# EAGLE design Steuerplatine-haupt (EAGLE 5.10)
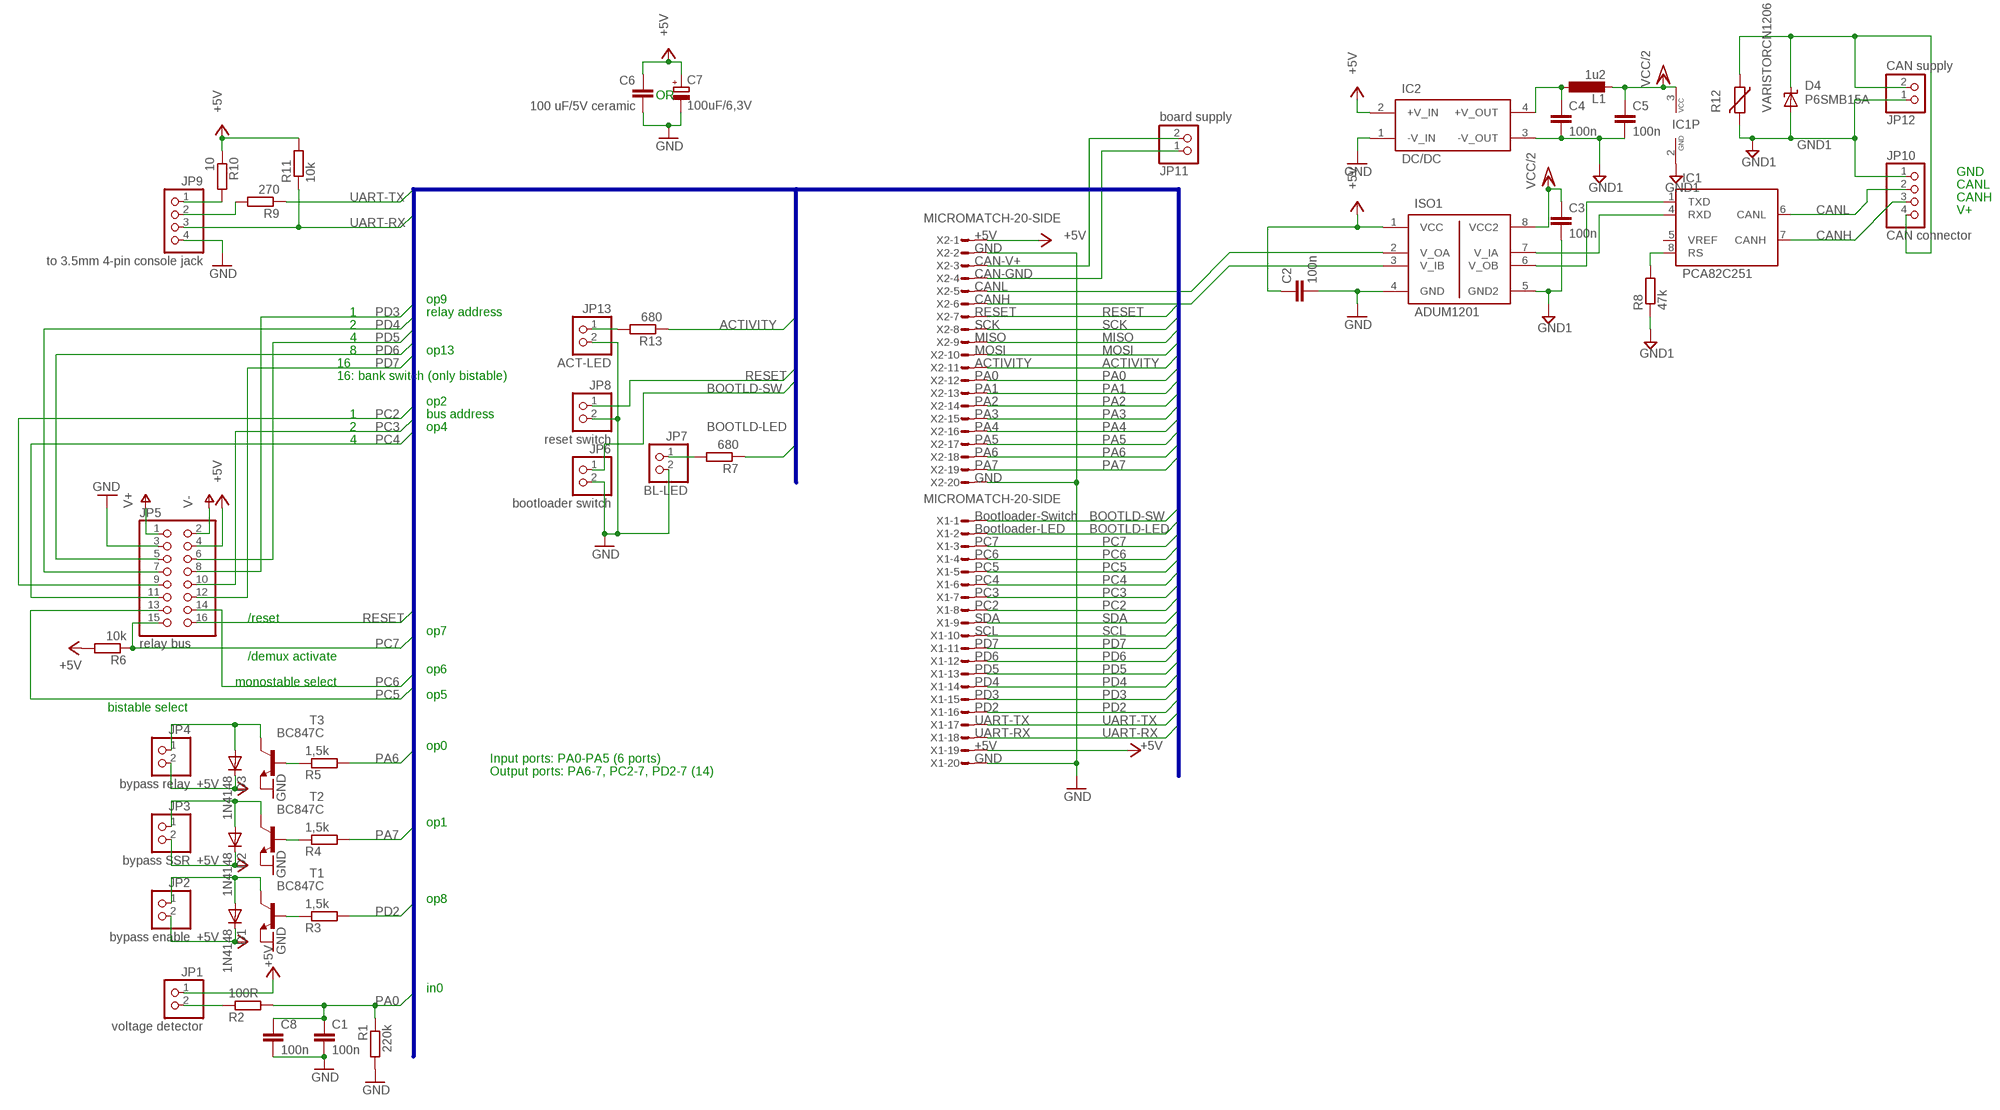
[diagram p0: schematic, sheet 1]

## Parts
C1  100n  C-EUC0805  [C0805]
C2  100n  C-EUC0805  [C0805]
C3  100n  C-EUC0805  [C0805]
C4  100n  C-EUC0805  [C0805]
C5  100n  C-EUC0805  [C0805]
C6  100 uF/5V ceramic  C-EUC1206  [C1206]
C7  100uF/6,3V  CPOL-EUD  [PANASONIC_D]
C8  100n  C-EUC0805  [C0805]
D1  1N4148  DIODE-SOD323-W  [SOD323-W]
D2  1N4148  DIODE-SOD323-W  [SOD323-W]
D3  1N4148  DIODE-SOD323-W  [SOD323-W]
D4  P6SMB15A  P6SMBXXA  [SMB]
IC1  PCA82C251  PCA82C250  [DIL08]
IC2  DC/DC  [DCDC-SIL4]
ISO1  ADUM1201  [SO08]
JP1  voltage detector  PINHD-1X2  [1X02]
JP2  bypass enable  PINHD-1X2  [1X02]
JP3  bypass SSR  PINHD-1X2  [1X02]
JP4  bypass relay  PINHD-1X2  [1X02]
JP5  relay bus  PINHD-2X8/90  [2X08/90]
JP6  bootloader switch  PINHD-1X2  [1X02]
JP7  BL-LED  PINHD-1X2  [1X02]
JP8  reset switch  PINHD-1X2  [1X02]
JP9  to 3.5mm 4-pin console jack  PINHD-1X4  [1X04]
JP10  CAN connector  PINHD-1X4  [1X04]
JP11  board supply  PINHD-1X2  [1X02]
JP12  CAN supply  PINHD-1X2  [1X02]
JP13  ACT-LED  PINHD-1X2  [1X02]
L1  1u2  L-EUL3216C  [L3216C]
R1  220k  R-EU_R0805  [R0805]
R2  100R  R-EU_R0805  [R0805]
R3  1,5k  R-EU_R0805  [R0805]
R4  1,5k  R-EU_R0805  [R0805]
R5  1,5k  R-EU_R0805  [R0805]
R6  10k  R-EU_R0805  [R0805]
R7  680  R-EU_R0805  [R0805]
R8  47k  R-EU_R0805  [R0805]
R9  270  R-EU_R0805  [R0805]
R10  10  R-EU_R0805  [R0805]
R11  10k  R-EU_R0805  [R0805]
R12  VARISTORCN1206  [CT/CN1206]
R13  680  R-EU_R0805  [R0805]
T1  BC847C  BC847BSMD  [SOT23]
T2  BC847C  BC847BSMD  [SOT23]
T3  BC847C  BC847BSMD  [SOT23]
X1  MICROMATCH-20-SIDE  [MICROMATCH-20-SIDE]
X2  MICROMATCH-20-SIDE  [MICROMATCH-20-SIDE]

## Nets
+5V: C2.1 C6.1 C7.+ D1.C D2.C D3.C IC2.2(+V_IN) ISO1.1(VCC) JP1.1 JP2.2 JP3.2 JP4.2 JP5.4 R6.2 R10.1 R11.2 X1.19 X2.1
ACTIVITY: R13.1 X2.11
BOOTLD-LED: R7.1 X1.2
BOOTLD-SW: JP6.1 X1.1
CAN-GND: JP11.1 X2.4
CAN-V+: JP11.2 X2.3
CAN_CONN_V+ [Power]: D4.C JP10.4 JP12.2 R12.1
CANH: IC1.7(CANH) JP10.3
CANH_TXD: ISO1.3(V_IB) X2.6
CANL: IC1.6(CANL) JP10.2
CANL_RXD: ISO1.2(V_OA) X2.5
GND: C1.2 C2.2 C6.2 C7.- C8.2 IC2.1(-V_IN) ISO1.4(GND) JP5.3 JP6.2 JP7.2 JP8.2 JP9.4 JP13.2 R1.2 T1.2(E) T2.2(E) T3.2(E) X1.20 X2.2 X2.20
GND1: C3.2 C4.2 C5.2 D4.A IC1.2(GND) IC2.3(-V_OUT) ISO1.5(GND2) JP10.1 JP12.1 R8.1 R12.2
MISO: X2.9
MOSI: X2.10
N$1: JP1.2 R2.1
N$2: JP9.2 R9.2
N$3: JP9.1 R10.2
N$4: JP13.1 R13.2
N$6: R3.1 T1.1(B)
N$7: D1.A JP2.1 T1.3(C)
N$8: IC1.4(RXD) ISO1.7(V_IA)
N$9: JP7.1 R7.2
N$10: R4.1 T2.1(B)
N$11: D3.A JP4.1 T3.3(C)
N$12: IC1.1(TXD) ISO1.6(V_OB)
N$13: D2.A JP3.1 T2.3(C)
N$14: C4.1 IC2.4(+V_OUT) L1.1
N$15: IC1.8(RS) R8.2
N$48: R5.1 T3.1(B)
PA0: C1.1 C8.1 R1.1 R2.2 X2.12
PA1: X2.13
PA2: X2.14
PA3: X2.15
PA4: X2.16
PA5: X2.17
PA6: R5.2 X2.18
PA7: R4.2 X2.19
PC2: JP5.9 X1.8
PC3: JP5.10 X1.7
PC4: JP5.11 X1.6
PC5: JP5.13 X1.5
PC6: JP5.14 X1.4
PC7: JP5.15 R6.1 X1.3
PD2: R3.2 X1.16
PD3: JP5.8 X1.15
PD4: JP5.7 X1.14
PD5: JP5.6 X1.13
PD6: JP5.5 X1.12
PD7: JP5.12 X1.11
RESET: JP5.16 JP8.1 X2.7
SCK: X2.8
SCL: X1.10
SDA: X1.9
UART-RX: JP9.3 R11.1 X1.18
UART-TX: R9.1 X1.17
V+: JP5.1
V-: JP5.2
VCC/2: C3.1 C5.1 IC1.3(VCC) ISO1.8(VCC2) L1.2
Unconnected: IC1.5(VREF)

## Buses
PA[0..7],PC[2..7],PD[2..7],SCK,MISO,MOSI,CAN-CS,BOOTLD-SW,CAN-INT,BOOTLD-LED,ACTIVITY,SDA,SCL,UART-RX,UART-TX,CLK,RESET

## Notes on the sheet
- OR
- GND
- CANL
- CANH
- V+
- +5V
- GND
- CAN-V+
- CAN-GND
- CANL
- op9 | CANH
- 1 | relay address | RESET
- 2 | SCK
- 4 | MISO
- 8 | op13 | MOSI
- 16 | ACTIVITY
- 16: bank switch (only bistable) | PA0
- PA1
- op2 | PA2
- 1 | bus address | PA3
- 2 | op4 | PA4
- 4 | PA5
- PA6
- PA7
- GND
- Bootloader-Switch
- Bootloader-LED
- PC7
- PC6
- PC5
- PC4
- PC3
- PC2
- /reset | SDA
- op7 | SCL
- PD7
- /demux activate | PD6
- op6 | PD5
- monostable select | PD4
- op5 | PD3
- bistable select | PD2
- UART-TX
- UART-RX
- op0 | +5V
- Input ports: PA0-PA5 (6 ports) | GND
- Output ports: PA6-7, PC2-7, PD2-7 (14)
- op1
- op8
- in0

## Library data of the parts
C1-C6 C8 = rcl:C-EU: CAPACITOR, European symbol
C7 = rcl:CPOL-EU: POLARIZED CAPACITOR, European symbol
D1-D3 = diode:DIODE-: DIODE
D4 = 11my-ICs:P6SMBXXA: Suppressor diode
IC1 = 11my-CAN:PCA82C250: PCA82C250 CAN Bustreiber
IC2 = 11my-ICs:DC/DC
ISO1 = 11my-ICs:ADUM1201: ADuM1201 Dual-Channel Digital Isolators zu beziehen per Sample oder bei Farnell
JP1-JP4 JP6-JP8 JP11-JP13 = pinhead:PINHD-1X2: PIN HEADER
JP5 = pinhead:PINHD-2X8: PIN HEADER
JP9 JP10 = pinhead:PINHD-1X4: PIN HEADER
L1 = rcl:L-EU: INDUCTOR, European symbol
R1-R11 R13 = rcl:R-EU_: RESISTOR, European symbol
R12 = varistor:VARISTOR: VARISTOR
T1-T3 = transistor-npn:BC847*: NPN Transistor
X1 X2 = apbteam_con-amp-micromatch:MICROMATCH-20: Micro-MaTch 20 Straight connector: Suited for both, female and male.

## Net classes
0 default: width 0.15 mm, clearance 0.3 mm
1 Power: width 0.5 mm, clearance 0.3 mm

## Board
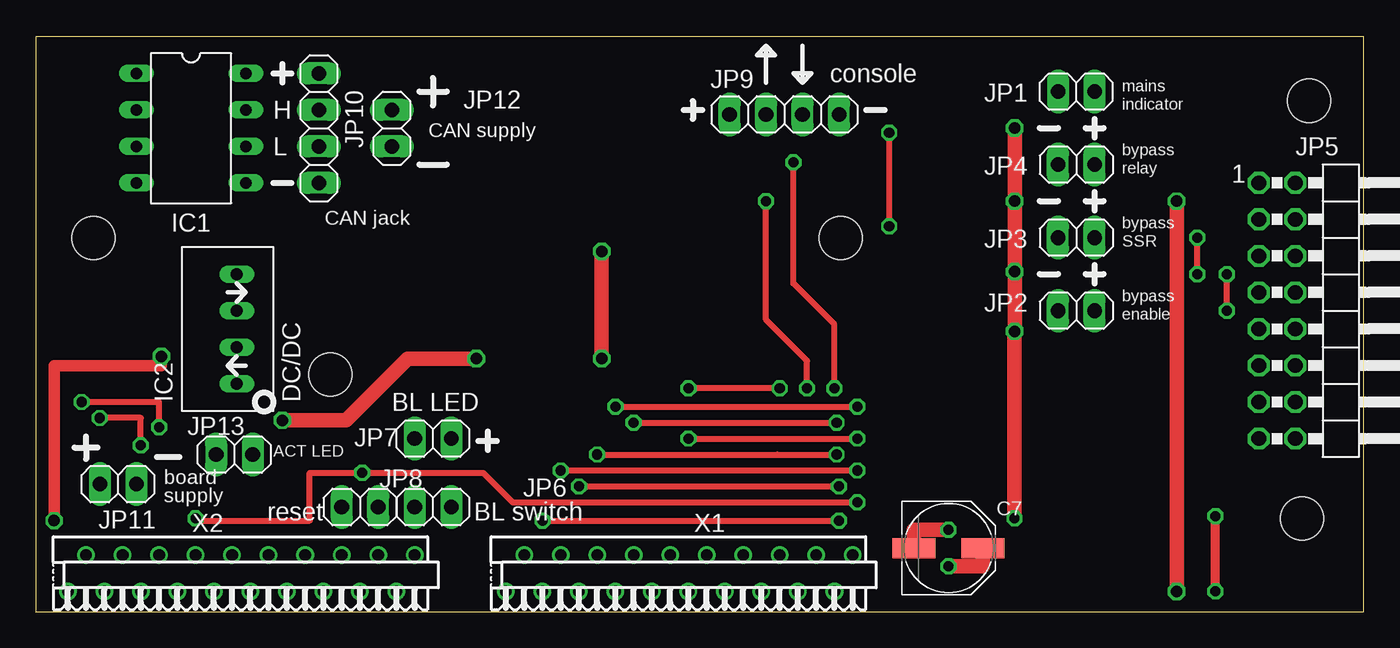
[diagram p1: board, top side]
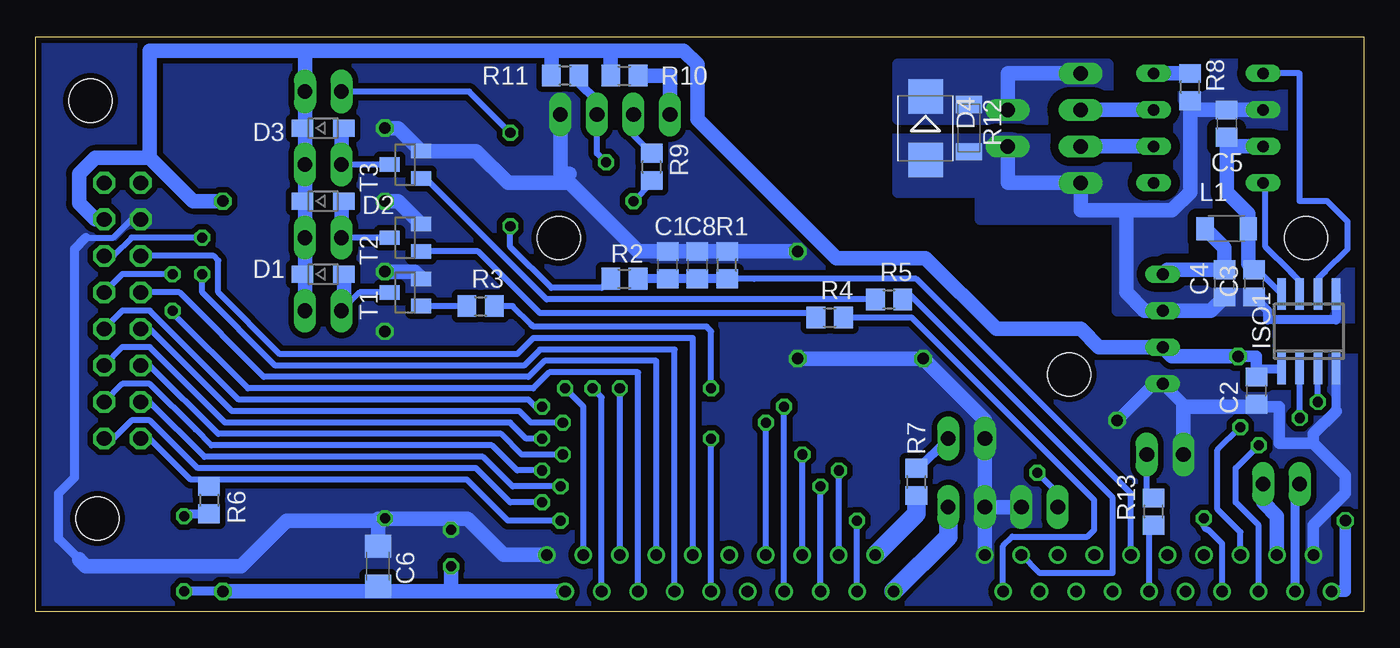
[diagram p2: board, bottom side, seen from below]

Size 92.38 x 40 mm. Coordinates in mm from the lower left corner, seen from the top.
Outline: 0,0 92.38,0 92.38,40 0,40 0,0
Copper layers (1+2*15+16): Top 0.035mm / dielectric 0.36mm / layer 2 0.018mm / dielectric 0.71mm / layer 15 0.018mm / dielectric 0.36mm / Bottom 0.035mm
Design rules "q-print.info *": minimum track width 6mil, minimum drill 0.3mm, track to track 6mil, track to pad 6mil, pad to pad 6mil, via to via 6mil, smd to smd 6mil, copper to edge 8mil, drill to drill 10mil, minimum pad ring 8mil, minimum via ring 8mil, stop-mask expansion 4mil, vias tented up to drill 16mil, thermal gap 10mil
Holes 3 mm at 4,26 56,26 20.48,16.51 88.58,35.56 88.11,6.51

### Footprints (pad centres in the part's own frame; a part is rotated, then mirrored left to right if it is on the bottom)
C0805 = smd 1.3 x 1.5: 1 -0.95,0; 2 0.95,0
C1206 = smd 1.6 x 1.8: 1 -1.4,0; 2 1.4,0
PANASONIC_D = smd 3 x 1.4: + 2.4,0; - -2.4,0
SOD323-W = smd 1.5 x 1.2: A 1.45,0; C -1.45,0
SMB = smd 2.4 x 2.4: A 2.2,0; C -2.2,0
DIL08 = drill 0.813 long: 1 -3.81,-3.81; 2 -1.27,-3.81; 3 1.27,-3.81; 4 3.81,-3.81; 5 3.81,3.81; 6 1.27,3.81; 7 -1.27,3.81; 8 -3.81,3.81
DCDC-SIL4 = drill 0.813 long: 1 -3.81,0; 2 -1.27,0; 3 1.27,0; 4 3.81,0
SO08 = smd 0.6 x 2.2: 1 -1.905,-2.6; 2 -0.635,-2.6; 3 0.635,-2.6; 4 1.905,-2.6; 5 1.905,2.6; 6 0.635,2.6; 7 -0.635,2.6; 8 -1.905,2.6
1X02 = drill 1.016 long: 1 -1.27,0; 2 1.27,0
2X08/90 = drill 1.016 octagon: 1 -8.89,-6.35; 2 -8.89,-3.81; 3 -6.35,-6.35; 4 -6.35,-3.81; 5 -3.81,-6.35; 6 -3.81,-3.81; 7 -1.27,-6.35; 8 -1.27,-3.81; 9 1.27,-6.35; 10 1.27,-3.81; 11 3.81,-6.35; 12 3.81,-3.81; 13 6.35,-6.35; 14 6.35,-3.81; 15 8.89,-6.35; 16 8.89,-3.81
1X04 = drill 1.016 long: 1 -3.81,0; 2 -1.27,0; 3 1.27,0; 4 3.81,0
L3216C = smd 1.2 x 1.6: 1 -1.5,0; 2 1.5,0
R0805 = smd 1.3 x 1.5: 1 -0.95,0; 2 0.95,0
CT/CN1206 = smd 1.2 x 1.8: 1 -1.65,0; 2 1.65,0
SOT23 = smd 1 x 1.4: 1 -0.95,-1.1; 2 0.95,-1.1; 3 0,1.1
MICROMATCH-20-SIDE = drill 0.813 round: 1 12.065,1.27; 2 10.795,-1.27; 3 9.525,1.27; 4 8.255,-1.27; 5 6.985,1.27; 6 5.715,-1.27; 7 4.445,1.27; 8 3.175,-1.27; 9 1.905,1.27; 10 0.635,-1.27; 11 -0.635,1.27; 12 -1.905,-1.27; 13 -3.175,1.27; 14 -4.445,-1.27; 15 -5.715,1.27; 16 -6.985,-1.27; 17 -8.255,1.27; 18 -9.525,-1.27; 19 -10.795,1.27; 20 -12.065,-1.27

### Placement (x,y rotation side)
C1  48.42,24.13 90 bottom
C2  7.46,15.4 270 bottom
C3  7.62,22.86 270 bottom
C4  9.68,22.86 270 bottom
C5  9.53,33.97 90 bottom
C6  68.58,3.18 90 bottom
C7  63.5,4.45 0 top
C8  46.35,24.13 90 bottom
D1  72.39,23.5 0 bottom
D2  72.39,28.57 0 bottom
D3  72.39,33.66 0 bottom
D4  30.48,33.66 270 bottom
IC1  10.79,33.66 270 top
IC2  13.97,19.68 90 top
ISO1  3.81,19.53 0 bottom
JP1  72.39,36.2 180 top
JP2  72.39,20.95 0 top
JP3  72.39,26.04 0 top
JP4  72.39,31.11 0 top
JP5  91.44,20.95 270 top
JP6  27.62,7.3 180 top
JP7  27.62,12.06 180 top
JP8  22.54,7.3 0 top
JP9  52.07,34.61 0 top
JP10  19.68,33.66 90 top
JP11  5.71,8.89 180 top
JP12  24.77,33.66 90 top
JP13  13.81,10.95 180 top
L1  9.53,26.67 0 bottom
R1  44.29,24.13 90 bottom
R2  51.44,23.18 0 bottom
R3  61.44,21.27 0 bottom
R4  37.15,20.48 0 bottom
R5  33.02,21.75 0 bottom
R6  80.33,7.78 270 bottom
R7  31.11,9.05 90 bottom
R8  12.06,36.51 90 bottom
R9  49.53,30.96 90 bottom
R10  51.44,37.31 0 bottom
R11  55.56,37.31 180 bottom
R12  27.46,33.66 270 bottom
R13  14.61,6.99 90 bottom
T1  66.67,22.23 90 bottom
T2  66.67,26.04 90 bottom
T3  66.67,31.11 90 bottom
X1  44.77,2.7 180 top
X2  14.29,2.7 180 top

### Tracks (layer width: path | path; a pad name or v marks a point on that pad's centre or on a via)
+5V  (via drill 0.7, 0.8)
  Top 0.61: v82.07,1.43 v82.07,6.67
  Top 0.813: v1.27,6.35 1.27,17.14 8.73,17.14 v8.73,17.78
  Top 1.016: v79.38,28.57 v79.38,1.43 | v63.5,3.17 65.9,3.17 C7.+
  Bottom 0.61: v79.38,1.43 v82.07,1.43 | ISO1.1 7.46,16.93 C2.1 | v82.07,6.67 81.91,6.83 R6.2
  Bottom 0.813: X2.1 1.27,1.43 v1.27,6.35 | v8.73,17.78 7.46,17.78 C2.1
  Bottom 1.016: 73.66,39.05 JP1.1 73.66,33.84 D3.C 73.66,33.48 JP4.2 73.66,28.75 D2.C 73.66,28.39 JP3.2 73.66,23.68 D1.C 73.66,23.32 JP2.2 | 56.59,39.05 73.66,39.05 | v79.38,1.43 68.58,1.43 | C6.1 | 68.58,1.43 C6.1 | 63.5,1.43 X1.19 | 68.58,1.43 63.5,1.43 | 63.5,1.43 v63.5,3.17 | 52.7,39.05 47.31,39.05 46.35,38.1 46.35,34.29 36.67,24.61 30.48,24.61 25.56,19.68 19.68,19.68 18.41,18.41 IC2.2 13.34,17.78 v8.73,17.78 | 52.7,39.05 56.59,39.05 | v79.38,28.57 81.44,28.57 84.45,31.59 | JP5.4 88.27,27.3 89.38,28.42 89.38,30.48 88.27,31.59 84.45,31.59 | 73.66,39.05 84.45,39.05 84.45,31.59 | R11.2 56.51,38.98 56.59,39.05 | R10.1 52.38,38.73 52.7,39.05
ACTIVITY
  Bottom 0.406: X2.11 14.92,6.04 R13.1
BOOTLD-LED
  Bottom 1.27: X1.2 31.11,6.83 R7.1
BOOTLD-SW
  Bottom 1.27: JP6.1 28.89,5.24 X1.1
CAN-GND
  Bottom 1.016: X2.4 6.03,6.67 6.99,7.62 JP11.1
CAN-V+
  Bottom 0.61: X2.3 4.76,8.57 JP11.2
CAN_CONN_V+
  Bottom 1.016: JP10.4 24.77,37.47 JP12.2
  pour Bottom (isolate 0.813, rank 2, no thermals): 17.78,34.29 32.38,34.29 32.38,38.1 17.78,38.1
CANH
  Bottom 1.016: IC1.7 JP10.3
CANH_TXD  (via drill 0.7)
  Top 0.406: v3.17,14.61 8.57,14.61 v8.57,12.86
  Bottom 0.406: ISO1.3 | v3.17,14.61 ISO1.3 | X2.6 8.57,5.56 10.16,7.14 10.16,11.27 v8.57,12.86
CANL
  Bottom 1.016: IC1.6 JP10.2
CANL_RXD  (via drill 0.7)
  Top 0.406: v4.45,13.49 7.3,13.49 v7.3,11.59
  Bottom 0.406: ISO1.2 | v4.45,13.49 ISO1.2 | X2.5 7.3,6.03 8.89,7.62 8.89,10 v7.3,11.59
GND  (via drill 0.7, 0.8)
  Top 1.016: v68.1,33.66 v68.1,28.57 v68.1,23.68 v68.1,19.53 v68.1,19.52 v68.1,6.51 | v63.5,5.71 61.1,5.71 C7.- | v39.37,17.62 v39.37,25.08 | v30.64,17.62 25.88,17.62 21.59,13.34 v17.14,13.34
  Bottom 0.406: 88.9,26.04 87,26.04 85.72,27.3 JP5.3
  Bottom 0.61: 88.9,26.04 89.69,25.24 89.69,9.37 90.81,8.26 90.81,5.08 89.38,3.65 | 1.91,13.97 ISO1.4
  Bottom 0.813: 3.49,11.75 5.87,11.75 5.87,14.29 7.46,14.29 | 3.49,11.75 3.49,12.38 1.91,13.97 | X2.2 3.49,6.03 1.27,8.26 1.27,9.53 3.49,11.75 | 12.06,14.29 12.38,14.29 IC2.1 14.61,15.88 v17.14,13.34
  Bottom 1.016: JP6.2 JP7.2 26.35,13.34 v30.64,17.62 v39.37,17.62 | JP6.2 JP8.2 | JP6.2 X2.20 | 55.24,30.48 | T1.2 65.55,23.2 66.03,23.68 v68.1,23.68 | 68.58,6.48 63.5,6.48 | C6.2 | C6.2 68.58,4.45 | 63.5,6.48 v63.5,5.71 | v39.37,25.08 R1.2 C8.2 C1.2 50.48,25.08 55.24,29.84 55.88,29.84 | T2.2 67.17,28.57 v68.1,28.57 | v68.1,33.66 67.17,33.66 T3.2 61.75,32.06 59.53,29.84 55.88,29.84 | 55.88,29.84 JP9.4 | 63.5,6.48 62.36,6.48 59.85,3.97 X1.20 | 68.58,6.48 | 68.58,6.35 68.58,6.48 | 68.58,6.35 C6.2 | 68.58,6.35 68.26,6.35 v68.1,6.51 | 68.58,6.48 68.71,6.35 | 68.71,6.35 74.93,6.35 78.11,3.17 88.9,3.17 89.38,3.65 | 89.38,3.65 | 68.58,6.35 68.71,6.35 | JP13.2 12.54,14.29 12.06,14.29 7.46,14.29 C2.2
  pour Bottom (isolate 0.4, no thermals): 0,0 92.71,0 92.71,39.37 46.99,39.37 37.47,29.53 25.88,17.78 0,17.78
GND1
  Bottom 0.61: ISO1.5 1.91,20.32 6.67,20.32 6.67,20.95 C3.2 | ISO1.5
  Bottom 1.016: 12.06,34.92 C5.2 IC1.2 | 12.06,34.92 R8.1 | JP12.1 24.77,29.84 JP10.1 19.68,27.94 16.51,27.94 | 16.51,27.94 13.34,27.94 12.06,29.21 12.06,34.92 | C4.2 10.64,20.95 IC2.3 15.24,20.95 16.51,22.23 16.51,27.94
  pour Bottom (isolate 0.61, rank 5, no thermals): 0.64,20.48 6.67,20.48 6.83,20.95 17.14,20.95 17.14,27.3 26.67,27.3 26.67,29.21 32.38,29.21 32.38,38.1 0.64,38.1
N$1  (via drill 0.7)
  Top 0.406: v59.37,26.83 v59.37,33.34
  Bottom 0.406: v59.37,26.83 59.37,25.4 56.52,22.54 53.02,22.54 R2.1 | v59.37,33.34 62.23,36.2 JP1.2
N$2
  Bottom 0.406: 50.8,33.49 50.8,33.18 R9.2
  Bottom 0.61: 50.8,33.49 JP9.2
N$3
  Bottom 1.016: JP9.1 48.26,37.31 R10.2
N$4
  Bottom 0.406: R13.2 arc90 15.08,8.41 JP13.1
N$6
  Bottom 0.406: T1.1 R3.1
N$7
  Bottom 0.406: T1.3 69.85,22.23 JP2.1
  Bottom 1.016: D1.A 70.94,21.14 JP2.1
N$8
  Bottom 0.406: ISO1.7 4.45,23.02 4.92,23.5 5.08,23.65 6.83,25.4 6.83,29.84 IC1.4
N$9
  Bottom 0.61: R7.2 31.11,9.84 JP7.1
N$10
  Bottom 0.406: T2.1 61.6,25.09 57.31,20.8 38.41,20.8 R4.1
N$11
  Bottom 0.406: T3.3 JP4.1
  Bottom 1.016: D3.A 71.12,33.48 JP4.1
N$12
  Bottom 0.406: ISO1.6 3.17,23.18 | 3.17,23.18 | 3.17,23.18 2.7,23.65 | 2.7,23.65 | IC1.1 4.45,37.47 4.45,28.57 2.54,28.57 1.11,27.15 1.11,25.24 2.7,23.65
N$13
  Bottom 0.406: T2.3 JP3.1
  Bottom 1.016: D2.A 71.12,28.39 JP3.1
N$14
  Bottom 1.016: L1.1 9.68,25.33 C4.1 13.65,23.81 IC2.4
N$15
  Bottom 1.016: R8.2 IC1.8
N$48
  Bottom 0.406: 65.25,30.16 T3.1 65.25,30.16 | R5.1 56.83,21.75 65.25,30.16
PA0
  Bottom 0.406: R1.1 42.39,23.18 31.11,23.18 16.19,8.26 | 16.19,8.26 | X2.12 16.19,8.26
  Bottom 0.61: C1.1 C8.1 R1.1 | C1.1 48.42,23.28 | C1.1 R2.2
PA6
  Bottom 0.406: X2.18 22.54,2.7 17.46,2.7 17.46,7.94 31.75,22.23 31.75,22.07 R5.2
PA7
  Bottom 0.406: R4.2 31.43,20.48 18.73,7.78 18.73,5.71 19.21,5.24 24.45,5.24 25.08,4.6 X2.19
PC2  (via drill 0.7)
  Top 0.406: v41.59,13.18 v55.72,13.18
  Bottom 0.406: JP5.9 84.45,19.68 78.74,13.97 58.74,13.97 57.94,13.18 v55.72,13.18 | v41.59,13.18 | X1.8 v41.59,13.18
PC3  (via drill 0.7)
  Top 0.406: v57.15,14.29 v40.32,14.29
  Bottom 0.406: JP5.10 86.36,20.95 84.45,20.95 78.26,14.76 58.1,14.76 57.63,14.29 v57.15,14.29 | v40.32,14.29 X1.7
PC4  (via drill 0.7)
  Top 0.406: v39.05,10.95 51.59,10.95 | 51.59,10.95 | 51.59,10.95 v55.72,10.95
  Bottom 0.406: JP5.11 84.45,17.14 79.69,12.38 60.01,12.38 58.58,10.95 v55.72,10.95 | v39.05,10.95 | X1.6 v39.05,10.95
PC5  (via drill 0.7)
  Top 0.406: v55.88,8.73 | v37.78,8.73 v55.88,8.73
  Bottom 0.406: JP5.13 84.45,14.61 80.64,10.79 61.28,10.79 | 61.28,10.79 | 61.28,10.79 59.21,8.73 v55.88,8.73 | v37.78,8.73 X1.5
PC6  (via drill 0.7)
  Top 0.406: v36.51,9.84 v57.15,9.84
  Bottom 0.406: JP5.14 86.36,15.88 84.45,15.88 81.28,12.7 | 81.28,12.7 | 81.28,12.7 80.17,11.59 60.64,11.59 58.9,9.84 v57.15,9.84 | v36.51,9.84 | X1.4 v36.51,9.84
PC7  (via drill 0.7)
  Top 0.406: v35.24,6.35 v55.88,6.35
  Bottom 0.406: JP5.15 84.45,12.06 81.6,9.21 79.85,9.21 | 79.85,9.21 R6.1 | 79.85,9.21 62.39,9.21 59.53,6.35 v55.88,6.35 | v35.24,6.35 X1.3
PD2  (via drill 0.7)
  Top 0.406: v51.75,15.56 v45.4,15.56
  Bottom 0.406: R3.2 59.21,21.27 57.94,20 | 57.94,20 | 57.94,20 57.78,19.84 45.72,19.84 45.4,19.53 v45.4,15.56 | X1.16 v51.75,15.56
PD3  (via drill 0.7)
  Top 0.406: v82.87,20.95 v82.87,23.5
  Bottom 0.406: X1.15 50.48,16.67 56.67,16.67 57.78,15.56 77.63,15.56 82.87,20.8 v82.87,20.95 | JP5.8 86.36,23.5 v82.87,23.5
PD4
  Bottom 0.406: JP5.7 82.39,22.23 76.52,16.35 58.1,16.35 56.99,17.46 49.21,17.46 X1.14
PD5  (via drill 0.7)
  Top 0.406: v80.8,23.5 v80.8,26.04
  Bottom 0.406: X1.13 47.94,18.26 57.31,18.26 58.42,17.14 75.72,17.14 80.8,22.23 v80.8,23.5 | v80.8,26.04 85.72,26.04 87,24.77 JP5.6
PD6
  Bottom 0.406: JP5.5 80.01,24.77 79.69,24.45 79.69,22.23 75.41,17.94 58.9,17.94 57.78,19.05 46.67,19.05 X1.12
PD7  (via drill 0.7)
  Top 0.406: v45.4,12.06 v57.15,12.06
  Bottom 0.406: JP5.12 86.36,18.41 84.45,18.41 79.22,13.18 59.37,13.18 58.26,12.06 v57.15,12.06 | v45.4,12.06 | X1.11 v45.4,12.06
RESET  (via drill 0.7)
  Top 0.406: v57.15,7.62 33.18,7.62 31.11,9.68 v22.7,9.68 19.05,9.68 19.05,6.35 11.27,6.35 arc-90 v11.11,6.51
  Bottom 0.406: JP5.16 87,12.06 85.72,13.34 84.45,13.34 81.12,10 61.75,10 59.37,7.62 v57.15,7.62 | X2.7 9.84,4.76 10.79,5.71 arc90 11.11,6.03 v11.11,6.51 | JP8.1 21.27,8.26 v22.7,9.68
UART-RX  (via drill 0.7)
  Top 0.406: 52.7,22.86 55.56,20 v55.56,15.56 | 52.7,22.86 | 52.7,22.86 v52.7,31.27
  Bottom 0.406: 53.34,33.81 JP9.3 53.34,31.91 v52.7,31.27 | v55.56,15.56 54.29,14.29 X1.18
  Bottom 0.61: JP9.3 53.34,35.56 54.61,36.83 R11.1
UART-TX  (via drill 0.7)
  Top 0.406: v53.66,15.56 53.66,17.46 50.8,20.32 v50.8,28.57
  Bottom 0.406: X1.17 53.02,14.92 v53.66,15.56 | v50.8,28.57 49.53,29.84 R9.1
VCC/2
  Bottom 0.406: ISO1.8 7.4,23.81 C3.1
  Bottom 1.016: IC1.3 9.53,32.38 C5.1 9.53,29.21 8.03,27.71 L1.2 8.03,24.21 C3.1

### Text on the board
tPlace: console | mains | indicator | H | CAN supply | L | bypass | relay | 1 | CAN jack | bypass | SSR | bypass | enable | BL LED | board | supply | reset | BL switch
tNames: ACT LED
